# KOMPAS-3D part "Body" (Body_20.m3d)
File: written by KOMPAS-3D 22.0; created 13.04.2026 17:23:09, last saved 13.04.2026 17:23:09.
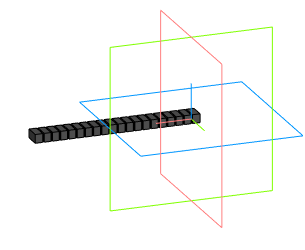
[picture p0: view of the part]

Document properties: Автор: Andrey; Полное имя файла: C:\Users\User1\Documents\Body_20.m3d

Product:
- Part/product: Body

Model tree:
1. Операция без истории:1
